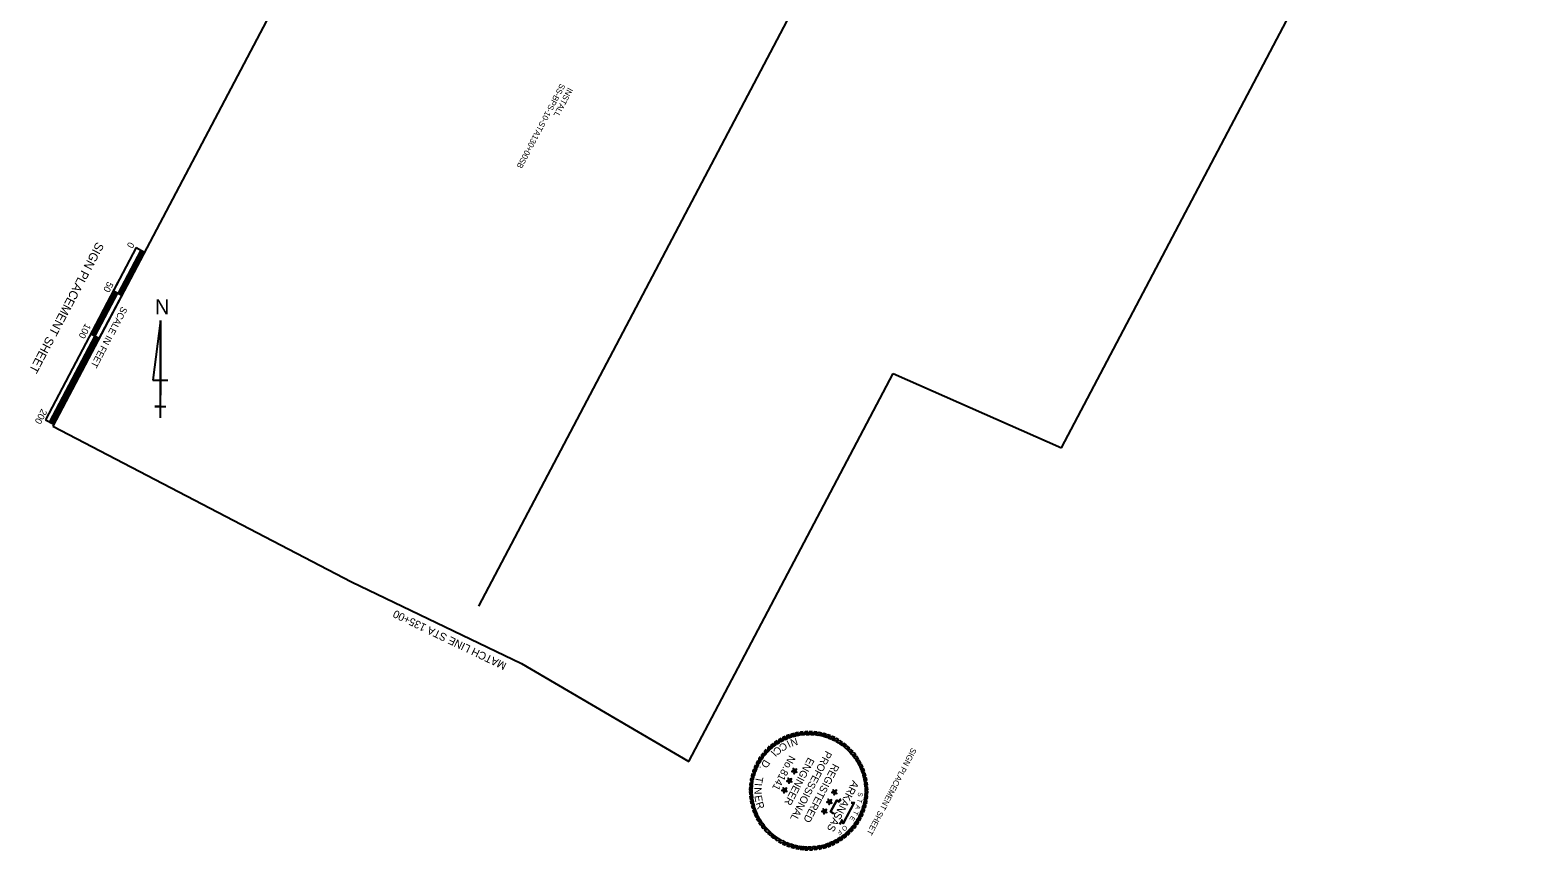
# Model space of a CAD drawing. Extents: x 980280 to 981831, y 1839841 to 1841608.
# Drawn here: x 980280 to 981831, y 1839841 to 1840684 of the extents above; entities that cross this region are included whole.
import ezdxf

# ---------------------------------------------------------------- set-up
doc = ezdxf.new("R2010")
doc.units = 0
for name, color, linetype in [('5', 7, 'Continuous'), ('63', 7, 'Continuous'), ('G-ANNO-SYMB', 7, 'Continuous'), ('G-ANNO-TEXT', 7, 'Continuous'), ('Level 10', 7, 'Continuous'), ('Plan Notes', 7, 'Continuous'), ('R_Annotation', 7, 'Continuous'), ('R_No Plot', 7, 'Continuous')]:
    doc.layers.add(name, color=color, linetype=linetype)

msp = doc.modelspace()

# ---------------------------------------------------------------- linework, layer by layer
at = {"layer": '5'}
msp.add_line((980610.6, 1840116.7), (980785.4, 1840032.8), dxfattribs=at)
at = {"layer": '63'}
for p, q in [((980414.1, 1840385.6), (980406.4, 1840324.1)), ((980414.1, 1840285.6), (980414.1, 1840385.6)), ((980414.1, 1840385.6), (980414.1, 1840308.7)), ((980406.4, 1840324.1), (980421.8, 1840324.1)), ((980414.1, 1840285.6), (980414.1, 1840308.7)), ((980414.1, 1840297.2), (980408.3, 1840297.2)), ((980408.3, 1840297.2), (980419.8, 1840297.2)), ((980414.1, 1840285.6), (980414.1, 1840297.2))]:
    msp.add_line(p, q, dxfattribs=at)
at = {"layer": 'G-ANNO-SYMB'}
for points in [[(981075.1, 1839962.6), (981072.5, 1839962.3), (981069.3, 1839958.9), (981072, 1839959.4)], [(981079.8, 1839962.8), (981077.2, 1839962.7), (981073.8, 1839959.6), (981076.6, 1839959.9)], [(981084.6, 1839962.7), (981082, 1839962.8), (981078.3, 1839960), (981081.1, 1839960)], [(981089.4, 1839962.2), (981086.8, 1839962.5), (981082.9, 1839960), (981085.7, 1839959.8)], [(981040.6, 1839947.7), (981038.7, 1839945.9), (981038, 1839941.3), (981040, 1839943.3)], [(981044.3, 1839950.7), (981042.2, 1839949.1), (981041.2, 1839944.5), (981043.4, 1839946.4)], [(981048.2, 1839953.4), (981046, 1839951.9), (981044.7, 1839947.5), (981047, 1839949.2)], [(981052.3, 1839955.8), (981050.1, 1839954.5), (981048.4, 1839950.2), (981050.8, 1839951.7)], [(981056.7, 1839957.8), (981054.3, 1839956.8), (981052.2, 1839952.6), (981054.7, 1839953.9)], [(981061.1, 1839959.6), (981058.7, 1839958.7), (981056.3, 1839954.6), (981058.9, 1839955.8)], [(981065.7, 1839960.9), (981063.2, 1839960.2), (981060.5, 1839956.4), (981063.2, 1839957.3)], [(981070.3, 1839961.9), (981067.8, 1839961.4), (981064.8, 1839957.8), (981067.6, 1839958.5)], [(981094.1, 1839961.3), (981091.5, 1839961.9), (981087.4, 1839959.7), (981090.2, 1839959.3)], [(981098.7, 1839960.1), (981096.2, 1839960.8), (981091.9, 1839959), (981094.7, 1839958.4)], [(981103.2, 1839958.5), (981100.7, 1839959.4), (981096.3, 1839957.9), (981099, 1839957.1)], [(981107.5, 1839956.6), (981105.2, 1839957.7), (981100.7, 1839956.5), (981103.3, 1839955.5)], [(981111.7, 1839954.3), (981109.5, 1839955.6), (981104.9, 1839954.8), (981107.4, 1839953.6)], [(981115.7, 1839951.7), (981113.6, 1839953.2), (981108.9, 1839952.7), (981111.4, 1839951.3)], [(981119.5, 1839948.8), (981117.5, 1839950.5), (981112.8, 1839950.4), (981115.1, 1839948.7)], [(981123.1, 1839945.7), (981121.2, 1839947.4), (981116.5, 1839947.7), (981118.7, 1839945.9)], [(981028.5, 1839933), (981027.2, 1839930.7), (981028, 1839926.2), (981029.2, 1839928.7)], [(981031, 1839937), (981029.6, 1839934.9), (981030, 1839930.2), (981031.5, 1839932.7)], [(981033.9, 1839940.8), (981032.3, 1839938.8), (981032.4, 1839934.1), (981034, 1839936.4)], [(981037.1, 1839944.4), (981035.3, 1839942.5), (981035.1, 1839937.8), (981036.9, 1839940)], [(981126.4, 1839942.2), (981124.6, 1839944.1), (981120, 1839944.8), (981122, 1839942.8)], [(981129.4, 1839938.5), (981127.8, 1839940.5), (981123.2, 1839941.5), (981125.1, 1839939.4)], [(981132.1, 1839934.6), (981130.7, 1839936.7), (981126.2, 1839938.1), (981127.9, 1839935.8)], [(981134.5, 1839930.4), (981133.2, 1839932.7), (981128.9, 1839934.4), (981130.4, 1839932)], [(981022.7, 1839919.9), (981021.9, 1839917.4), (981023.8, 1839913.2), (981024.4, 1839915.9)], [(981024.2, 1839924.5), (981023.3, 1839922), (981024.9, 1839917.6), (981025.7, 1839920.3)], [(981026.2, 1839928.8), (981025.1, 1839926.4), (981026.3, 1839921.9), (981027.3, 1839924.6)], [(981066.2, 1839922.3), (981065.2, 1839922.8), (981063.4, 1839921.9), (981065.4, 1839921.5)], [(981066.2, 1839922.3), (981066.3, 1839923.3), (981064.9, 1839924.8), (981065.2, 1839922.8)], [(981066.2, 1839922.3), (981065.4, 1839921.5), (981065.7, 1839919.5), (981066.6, 1839921.3)], [(981066.2, 1839922.3), (981067.2, 1839922.4), (981068.2, 1839924.2), (981066.3, 1839923.3)], [(981066.2, 1839922.3), (981066.6, 1839921.3), (981068.6, 1839921), (981067.2, 1839922.4)], [(981136.6, 1839926.1), (981135.5, 1839928.5), (981131.3, 1839930.5), (981132.6, 1839928)], [(981138.3, 1839921.7), (981137.4, 1839924.1), (981133.4, 1839926.5), (981134.5, 1839923.9)], [(981139.6, 1839917.1), (981138.9, 1839919.6), (981135.1, 1839922.3), (981136, 1839919.6)], [(981140.6, 1839912.4), (981140.1, 1839915), (981136.5, 1839917.9), (981137.2, 1839915.2)], [(981020.1, 1839905.9), (981020, 1839903.3), (981022.8, 1839899.6), (981022.7, 1839902.4)], [(981020, 1839901.1), (981020.1, 1839898.5), (981023.2, 1839895), (981022.9, 1839897.8)], [(981020.6, 1839910.6), (981020.3, 1839908), (981022.8, 1839904.1), (981022.9, 1839906.9)], [(981021.4, 1839915.3), (981020.9, 1839912.8), (981023.1, 1839908.7), (981023.5, 1839911.5)], [(981055.8, 1839902.6), (981054.9, 1839903.1), (981053.1, 1839902.2), (981055, 1839901.9)], [(981055.8, 1839902.6), (981056, 1839903.7), (981054.6, 1839905.1), (981054.9, 1839903.1)], [(981055.8, 1839902.6), (981055, 1839901.9), (981055.3, 1839899.9), (981056.3, 1839901.7)], [(981055.8, 1839902.6), (981056.9, 1839902.8), (981057.8, 1839904.5), (981056, 1839903.7)], [(981055.8, 1839902.6), (981056.3, 1839901.7), (981058.3, 1839901.3), (981056.9, 1839902.8)], [(981061, 1839912.4), (981060, 1839912.9), (981058.2, 1839912), (981060.2, 1839911.7)], [(981061, 1839912.4), (981061.2, 1839913.5), (981059.8, 1839914.9), (981060, 1839912.9)], [(981061, 1839912.4), (981060.2, 1839911.7), (981060.5, 1839909.7), (981061.5, 1839911.5)], [(981061, 1839912.4), (981062, 1839912.6), (981063, 1839914.4), (981061.2, 1839913.5)], [(981061, 1839912.4), (981061.5, 1839911.5), (981063.4, 1839911.1), (981062, 1839912.6)], [(981107.4, 1839900.6), (981106.4, 1839901.1), (981104.6, 1839900.2), (981106.6, 1839899.8)], [(981107.4, 1839900.6), (981107.5, 1839901.6), (981106.1, 1839903.1), (981106.4, 1839901.1)], [(981107.4, 1839900.6), (981106.6, 1839899.8), (981106.9, 1839897.8), (981107.8, 1839899.6)], [(981107.4, 1839900.6), (981108.4, 1839900.7), (981109.3, 1839902.5), (981107.5, 1839901.6)], [(981107.4, 1839900.6), (981107.8, 1839899.6), (981109.8, 1839899.3), (981108.4, 1839900.7)], [(981141.3, 1839907.7), (981141, 1839910.3), (981137.6, 1839913.5), (981138.1, 1839910.7)], [(981141.5, 1839902.9), (981141.4, 1839905.5), (981138.3, 1839909), (981138.6, 1839906.2)], [(981141.4, 1839898.2), (981141.5, 1839900.8), (981138.7, 1839904.5), (981138.8, 1839901.7)], [(981020.2, 1839896.4), (981020.5, 1839893.8), (981023.9, 1839890.5), (981023.4, 1839893.3)], [(981020.9, 1839891.6), (981021.4, 1839889.1), (981025, 1839886.1), (981024.3, 1839888.8)], [(981021.9, 1839887), (981022.6, 1839884.4), (981026.4, 1839881.8), (981025.5, 1839884.4)], [(981102.2, 1839890.7), (981101.2, 1839891.2), (981099.4, 1839890.3), (981101.4, 1839890)], [(981102.2, 1839890.7), (981102.4, 1839891.8), (981100.9, 1839893.2), (981101.2, 1839891.2)], [(981102.2, 1839890.7), (981101.4, 1839890), (981101.7, 1839888), (981102.6, 1839889.8)], [(981102.2, 1839890.7), (981103.2, 1839890.9), (981104.2, 1839892.7), (981102.4, 1839891.8)], [(981102.2, 1839890.7), (981102.6, 1839889.8), (981104.6, 1839889.4), (981103.2, 1839890.9)], [(981137.3, 1839879.6), (981138.2, 1839882.1), (981136.6, 1839886.5), (981135.8, 1839883.8)], [(981138.8, 1839884.1), (981139.6, 1839886.6), (981137.7, 1839890.9), (981137.1, 1839888.1)], [(981140.1, 1839888.7), (981140.6, 1839891.3), (981138.4, 1839895.4), (981138, 1839892.6)], [(981140.9, 1839893.4), (981141.2, 1839896), (981138.7, 1839899.9), (981138.6, 1839897.1)], [(981023.2, 1839882.4), (981024.1, 1839879.9), (981028.1, 1839877.6), (981027, 1839880.2)], [(981024.9, 1839877.9), (981026, 1839875.6), (981030.2, 1839873.5), (981028.9, 1839876)], [(981027, 1839873.6), (981028.3, 1839871.3), (981032.6, 1839869.6), (981031.1, 1839872)], [(981029.4, 1839869.5), (981030.8, 1839867.3), (981035.3, 1839866), (981033.6, 1839868.2)], [(981097, 1839880.9), (981096, 1839881.4), (981094.2, 1839880.5), (981096.2, 1839880.2)], [(981097, 1839880.9), (981097.2, 1839882), (981095.8, 1839883.4), (981096, 1839881.4)], [(981097, 1839880.9), (981096.2, 1839880.2), (981096.5, 1839878.2), (981097.5, 1839880)], [(981097, 1839880.9), (981098, 1839881.1), (981099, 1839882.8), (981097.2, 1839882)], [(981097, 1839880.9), (981097.5, 1839880), (981099.4, 1839879.6), (981098, 1839881.1)], [(981127.6, 1839863.2), (981129.2, 1839865.3), (981129.1, 1839869.9), (981127.5, 1839867.6)], [(981130.5, 1839867), (981131.9, 1839869.2), (981131.5, 1839873.8), (981130, 1839871.4)], [(981133.1, 1839871), (981134.3, 1839873.3), (981133.5, 1839877.9), (981132.3, 1839875.4)], [(981135.3, 1839875.2), (981136.4, 1839877.6), (981135.2, 1839882.1), (981134.2, 1839879.5)], [(981032.1, 1839865.6), (981033.7, 1839863.5), (981038.3, 1839862.5), (981036.4, 1839864.6)], [(981035.1, 1839861.9), (981036.9, 1839859.9), (981041.5, 1839859.3), (981039.5, 1839861.3)], [(981038.4, 1839858.4), (981040.3, 1839856.6), (981045, 1839856.4), (981042.8, 1839858.2)], [(981042, 1839855.2), (981044, 1839853.6), (981048.7, 1839853.7), (981046.4, 1839855.3)], [(981109.2, 1839848.3), (981111.4, 1839849.6), (981113.1, 1839853.9), (981110.8, 1839852.4)], [(981113.3, 1839850.7), (981115.5, 1839852.1), (981116.8, 1839856.6), (981114.6, 1839854.9)], [(981117.2, 1839853.4), (981119.3, 1839855), (981120.3, 1839859.6), (981118.2, 1839857.7)], [(981120.9, 1839856.4), (981122.8, 1839858.2), (981123.5, 1839862.8), (981121.5, 1839860.7)], [(981124.4, 1839859.7), (981126.2, 1839861.6), (981126.4, 1839866.3), (981124.6, 1839864.1)], [(981045.8, 1839852.3), (981047.9, 1839850.9), (981052.6, 1839851.3), (981050.1, 1839852.8)], [(981049.8, 1839849.7), (981052, 1839848.4), (981056.6, 1839849.3), (981054.1, 1839850.5)], [(981054, 1839847.5), (981056.3, 1839846.4), (981060.8, 1839847.5), (981058.2, 1839848.6)], [(981058.3, 1839845.5), (981060.8, 1839844.6), (981065.2, 1839846.1), (981062.5, 1839847)], [(981062.8, 1839843.9), (981065.3, 1839843.2), (981069.6, 1839845.1), (981066.9, 1839845.7)], [(981067.4, 1839842.7), (981070, 1839842.2), (981074.1, 1839844.4), (981071.3, 1839844.8)], [(981072.1, 1839841.8), (981074.7, 1839841.5), (981078.7, 1839844.1), (981075.8, 1839844.2)], [(981076.9, 1839841.4), (981079.5, 1839841.2), (981083.2, 1839844.1), (981080.4, 1839844)], [(981081.7, 1839841.2), (981084.3, 1839841.3), (981087.8, 1839844.4), (981084.9, 1839844.2)], [(981086.4, 1839841.5), (981089, 1839841.8), (981092.2, 1839845.2), (981089.5, 1839844.7)], [(981091.2, 1839842.1), (981093.7, 1839842.6), (981096.7, 1839846.2), (981093.9, 1839845.5)], [(981095.8, 1839843.1), (981098.3, 1839843.8), (981101, 1839847.7), (981098.3, 1839846.7)], [(981100.4, 1839844.5), (981102.9, 1839845.4), (981105.2, 1839849.4), (981102.6, 1839848.3)], [(981104.9, 1839846.2), (981107.2, 1839847.3), (981109.3, 1839851.5), (981106.8, 1839850.2)]]:
    msp.add_lwpolyline(points, close=True, dxfattribs=at)
for points in [[(981106.3, 1839877.8), (981106.2, 1839878.4), (981105.8, 1839878.7), (981104.7, 1839879.5), (981103.2, 1839880.2), (981109.6, 1839892.4), (981111.6, 1839891.3), (981112.1, 1839891), (981112.5, 1839891.5), (981113.4, 1839893.2), (981114, 1839893.2)], [(981106.7, 1839877.9), (981106.5, 1839878.6), (981106, 1839879), (981104.9, 1839879.8), (981103.7, 1839880.4), (981109.8, 1839891.8), (981111.4, 1839890.9), (981112.1, 1839890.6), (981112.8, 1839891.2), (981113.6, 1839892.8), (981114.1, 1839892.9)], [(981124.3, 1839889.7), (981127.1, 1839889.5), (981116.3, 1839869.1), (981115, 1839872.1), (981113.9, 1839869.9), (981113.2, 1839868.7), (981112.5, 1839867.5)], [(981124.3, 1839890.1), (981127.7, 1839889.9), (981116.3, 1839868.2), (981115, 1839871.2), (981114.2, 1839869.7), (981113.6, 1839868.5), (981112.8, 1839867.3)]]:
    msp.add_lwpolyline(points, dxfattribs=at)
at = {"layer": 'Level 10'}
for p, q in [((980389.1, 1840460.4), (980295.8, 1840283.4)), ((980389.1, 1840460.4), (980397.6, 1840455.9)), ((980397.6, 1840455.9), (980323, 1840314.3)), ((980394, 1840457.8), (980370.7, 1840413.5)), ((980394.7, 1840457.4), (980371.4, 1840413.2)), ((980395.4, 1840457), (980372.1, 1840412.8)), ((980396.2, 1840456.6), (980372.8, 1840412.4)), ((980396.9, 1840456.3), (980373.6, 1840412)), ((980397.6, 1840455.9), (980378.9, 1840420.5)), ((980366.5, 1840415.8), (980343.2, 1840371.5)), ((980367.2, 1840415.4), (980343.9, 1840371.2)), ((980367.9, 1840415), (980344.6, 1840370.8)), ((980368.6, 1840414.6), (980345.3, 1840370.4)), ((980369.3, 1840414.3), (980346, 1840370)), ((980370, 1840413.9), (980346.7, 1840369.7)), ((980370.4, 1840425), (980351.8, 1840389.6)), ((980365.8, 1840416.1), (980374.3, 1840411.7)), ((980360.3, 1840385.1), (980304.3, 1840279)), ((980346.7, 1840369.7), (980300.1, 1840281.2)), ((980347.4, 1840369.3), (980300.8, 1840280.8)), ((980348.1, 1840368.9), (980301.5, 1840280.4)), ((980348.8, 1840368.5), (980302.2, 1840280.1)), ((980349.5, 1840368.2), (980302.9, 1840279.7)), ((980350.2, 1840367.8), (980303.6, 1840279.3)), ((980346.7, 1840369.7), (980318.7, 1840316.6)), ((980342.5, 1840371.9), (980350.9, 1840367.4)), ((980295.8, 1840283.4), (980304.3, 1840279))]:
    msp.add_line(p, q, dxfattribs=at)
at = {"layer": 'R_No Plot'}
for p, q in [((981005, 1841608.4), (980303.4, 1840276.8)), ((981423.9, 1841387.7), (980741.2, 1840091.9)), ((981340.8, 1840254.6), (981830.7, 1841184.4)), ((980957.5, 1839932.2), (981167.6, 1840331.1)), ((981167.6, 1840331.1), (981340.8, 1840254.6))]:
    msp.add_line(p, q, dxfattribs=at)
msp.add_lwpolyline([(980303.4, 1840276.8), (980610.6, 1840116.7), (980785.4, 1840032.8), (980957.5, 1839932.2)], dxfattribs=at)

# ---------------------------------------------------------------- texts
at = {"layer": '63'}
msp.add_text('N', height=15.4, dxfattribs=at).set_placement((980408.4, 1840392))
at = {"layer": 'G-ANNO-SYMB'}
for s, height, rotation, p in [('C', 7.64, 218.733, (981049.2, 1839948.4)), ('C', 7.64, 210.9048, (981055.8, 1839952.3)), ('I', 7.64, 206.4316, (981059.8, 1839954.1)), ('N', 7.64, 197.4851, (981068.1, 1839956.7)), ('D', 7.64, 238.8626, (981035.1, 1839934.7)), ('I', 7.64, 226.5612, (981043.1, 1839943.7)), ('No.8141', 7.61, 242.2175, (981060.9, 1839939)), ('ENGINEER', 7.64, 242.2175, (981080.3, 1839936.8)), ('PROFESSIONAL', 7.642, 242.2175, (981098.4, 1839943.7)), ('T', 7.64, 258.9922, (981026.7, 1839917)), ('.', 7.64, 247.0635, (981030.9, 1839927.8)), ('REGISTERED', 7.64, 242.2175, (981105.9, 1839930.5)), ('N', 7.64, 270.9208, (981024.8, 1839905.5)), ('I', 7.64, 266.4476, (981025.2, 1839909.9)), ('ARKANSAS', 7.89, 242.2175, (981126, 1839913.4)), ('S', 4.84, 261.9901, (981131.7, 1839900.6)), ('E', 7.64, 279.8673, (981024.9, 1839896.7)), ('R', 7.64, 287.6955, (981026.1, 1839889.2)), ('A', 4.84, 250.8963, (981129.9, 1839888)), ('T', 4.84, 259.119, (981131.3, 1839893.9)), ('E', 4.84, 238.8895, (981124.8, 1839876.6)), ('T', 4.84, 243.6964, (981127.8, 1839882)), ('F', 4.84, 217.5803, (981112.6, 1839862.4)), ('O', 4.84, 223.4393, (981117.9, 1839867))]:
    msp.add_text(s, height=height, rotation=rotation, dxfattribs=at).set_placement(p)
at = {"layer": 'G-ANNO-TEXT'}
for height, p in [(9, (980348.5, 1840466.9)), (6, (981186.7, 1839946.7))]:
    msp.add_text('SIGN PLACEMENT SHEET', height=height, rotation=242.2175, dxfattribs=at).set_placement(p)
at = {"layer": 'Level 10'}
for s, height, p in [('0', 7, (980381.6, 1840466.9)), ('50', 7, (980359.9, 1840426.1)), ('SCALE IN FEET', 7.001, (980374.3, 1840400.4)), ('100', 7, (980336.9, 1840383.1)), ('200', 7, (980291.8, 1840295.2))]:
    msp.add_text(s, height=height, rotation=242.2178, dxfattribs=at).set_placement(p)
at = {"layer": 'Plan Notes'}
msp.add_text('MATCH LINE STA 135+00', height=8, rotation=154.3699, dxfattribs=at).set_placement((980770.7, 1840033))
at = {"layer": 'R_Annotation'}
for s, p in [('SS-BPS-10-STA130+00SB', (980825.4, 1840629.7)), ('INSTALL', (980833.3, 1840625.5))]:
    msp.add_text(s, height=6, rotation=242.2175, dxfattribs=at).set_placement(p)

doc.saveas('drawing.dxf')
